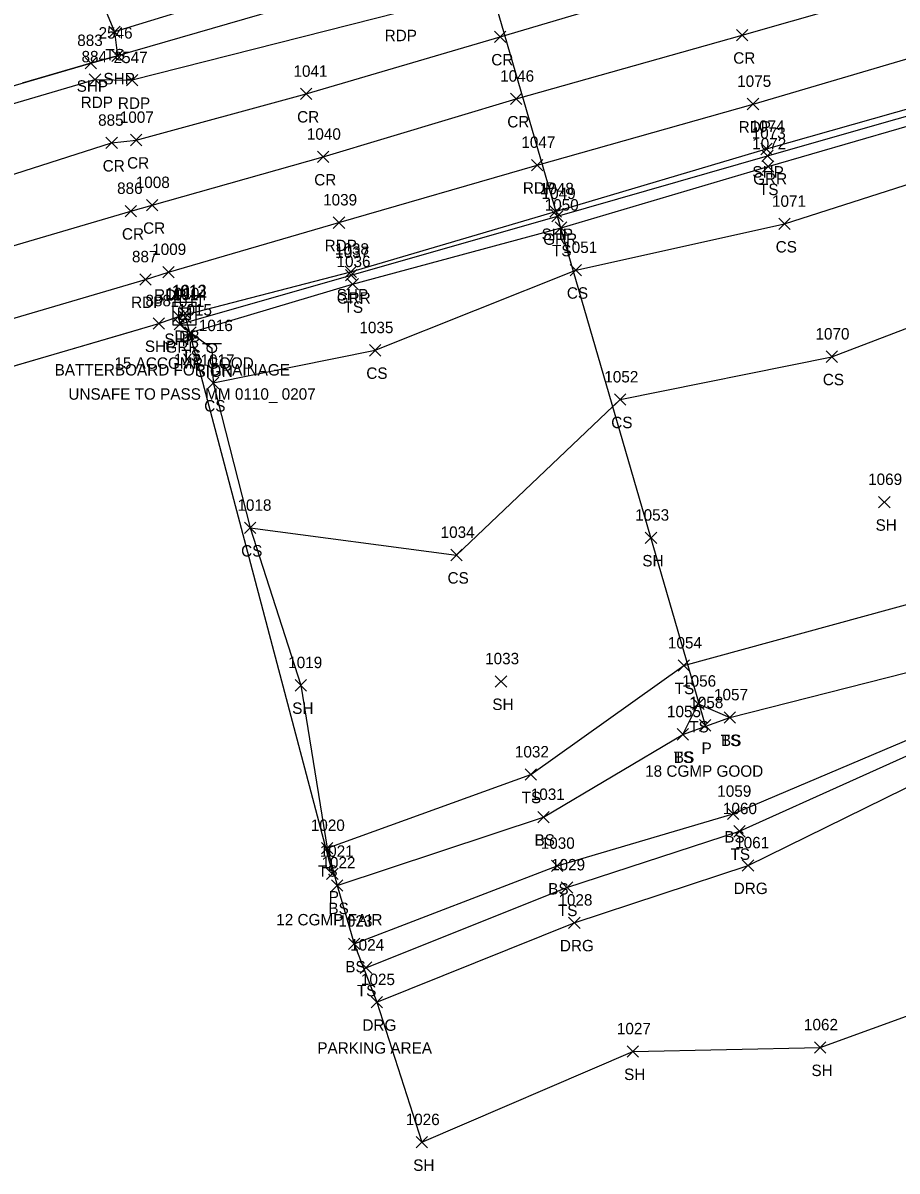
# Model space of a CAD drawing. Extents: x 49137 to 50946, y 9590 to 10709.
# Drawn here: x 49615.7 to 49768.6, y 9758.1 to 9959 of the extents above; entities that cross this region are included whole.
import ezdxf

# ---------------------------------------------------------------- set-up
doc = ezdxf.new("R2010")
doc.units = 0
for name, color, linetype in [('D_A', 7, 'Continuous'), ('D_C', 7, 'Continuous'), ('D_I', 7, 'Continuous'), ('D_TIC', 7, 'Continuous'), ('DCP', 7, 'Continuous'), ('DS', 7, 'Continuous'), ('L_A', 7, 'Continuous'), ('L_I', 7, 'Continuous'), ('L_TIC', 7, 'Continuous'), ('LELB', 7, 'Continuous'), ('LSOGP', 7, 'Continuous'), ('P_A', 7, 'Continuous'), ('P_I', 7, 'Continuous'), ('P_TIC', 7, 'Continuous'), ('PET', 7, 'Continuous'), ('PRC', 7, 'Continuous'), ('PSP', 7, 'Continuous'), ('R_A', 7, 'Continuous'), ('R_C', 7, 'Continuous'), ('R_I', 7, 'Continuous'), ('R_TIC', 7, 'Continuous'), ('RDG', 7, 'Continuous'), ('RGR', 7, 'Continuous'), ('S_A', 7, 'Continuous'), ('S_C', 7, 'Continuous'), ('S_I', 7, 'Continuous'), ('SSGN', 7, 'Continuous')]:
    doc.layers.add(name, color=color, linetype=linetype)

msp = doc.modelspace()

# ---------------------------------------------------------------- linework, layer by layer
at = {"layer": 'D_TIC'}
for points in [[(49643.11, 9907.2), (49645.11, 9909.2)], [(49645.11, 9907.2), (49643.11, 9909.2)], [(49643.13, 9906.49), (49645.13, 9908.49)], [(49645.13, 9906.49), (49643.13, 9908.49)], [(49734.05, 9835.12), (49736.05, 9837.12)], [(49736.05, 9835.12), (49734.05, 9837.12)], [(49668.84, 9809.12), (49670.84, 9811.12)], [(49670.84, 9809.12), (49668.84, 9811.12)]]:
    msp.add_lwpolyline(points, dxfattribs=at)
at = {"layer": 'DCP'}
for points in [[(49691.29, 9986.82), (49735.05, 9836.12)], [(49644.13, 9907.49), (49669.84, 9810.12)]]:
    msp.add_lwpolyline(points, dxfattribs=at)
at = {"layer": 'DS'}
for p, q in [((49641.97, 9910.13), (49645.97, 9910.13)), ((49641.97, 9906.13), (49641.97, 9910.13)), ((49645.97, 9910.13), (49645.97, 9906.13)), ((49642.97, 9907.13), (49642.97, 9909.13)), ((49642.97, 9909.13), (49644.97, 9909.13)), ((49643.98, 9908.13), (49643.98, 9908.13)), ((49643.98, 9908.13), (49643.98, 9908.13)), ((49644.97, 9909.13), (49644.97, 9907.13)), ((49645.97, 9906.13), (49641.97, 9906.13)), ((49644.97, 9907.13), (49642.97, 9907.13))]:
    msp.add_line(p, q, dxfattribs=at)
at = {"layer": 'L_TIC'}
for points in [[(49630.72, 9956.44), (49632.72, 9958.44)], [(49632.72, 9956.44), (49630.72, 9958.44)], [(49745.05, 9932.87), (49747.05, 9934.87)], [(49747.05, 9932.87), (49745.05, 9934.87)], [(49708.84, 9922.17), (49710.84, 9924.17)], [(49710.84, 9922.17), (49708.84, 9924.17)], [(49747.94, 9922.83), (49749.94, 9924.83)], [(49749.94, 9922.83), (49747.94, 9924.83)], [(49711.42, 9914.75), (49713.42, 9916.75)], [(49713.42, 9914.75), (49711.42, 9916.75)], [(49672.39, 9912.28), (49674.39, 9914.28)], [(49674.39, 9912.28), (49672.39, 9914.28)], [(49644.04, 9903.81), (49646.04, 9905.81)], [(49646.04, 9903.81), (49644.04, 9905.81)], [(49676.34, 9900.72), (49678.34, 9902.72)], [(49678.34, 9900.72), (49676.34, 9902.72)], [(49756.19, 9899.61), (49758.19, 9901.61)], [(49758.19, 9899.61), (49756.19, 9901.61)], [(49647.99, 9895.01), (49649.99, 9897.01)], [(49649.99, 9895.01), (49647.99, 9897.01)], [(49719.18, 9892.1), (49721.18, 9894.1)], [(49721.18, 9892.1), (49719.18, 9894.1)], [(49765.38, 9874.16), (49767.38, 9876.16)], [(49767.38, 9874.16), (49765.38, 9876.16)], [(49654.45, 9869.65), (49656.45, 9871.65)], [(49656.45, 9869.65), (49654.45, 9871.65)], [(49724.58, 9867.92), (49726.58, 9869.92)], [(49726.58, 9867.92), (49724.58, 9869.92)], [(49690.55, 9864.91), (49692.55, 9866.91)], [(49692.55, 9864.91), (49690.55, 9866.91)], [(49730.32, 9845.57), (49732.32, 9847.57)], [(49732.32, 9845.57), (49730.32, 9847.57)], [(49663.33, 9842.12), (49665.33, 9844.12)], [(49665.33, 9842.12), (49663.33, 9844.12)], [(49698.34, 9842.8), (49700.34, 9844.8)], [(49700.34, 9842.8), (49698.34, 9844.8)], [(49732.85, 9838.88), (49734.85, 9840.88)], [(49734.85, 9838.88), (49732.85, 9840.88)], [(49738.37, 9836.49), (49740.37, 9838.49)], [(49740.37, 9836.49), (49738.37, 9838.49)], [(49738.37, 9836.49), (49740.37, 9838.49)], [(49740.37, 9836.49), (49738.37, 9838.49)], [(49730.14, 9833.54), (49732.14, 9835.54)], [(49732.14, 9833.54), (49730.14, 9835.54)], [(49730.14, 9833.54), (49732.14, 9835.54)], [(49732.14, 9833.54), (49730.14, 9835.54)], [(49703.55, 9826.5), (49705.55, 9828.5)], [(49705.55, 9826.5), (49703.55, 9828.5)], [(49705.76, 9819.06), (49707.76, 9821.06)], [(49707.76, 9819.06), (49705.76, 9821.06)], [(49738.95, 9819.62), (49740.95, 9821.62)], [(49740.95, 9819.62), (49738.95, 9821.62)], [(49740.07, 9816.58), (49742.07, 9818.58)], [(49742.07, 9816.58), (49740.07, 9818.58)], [(49667.93, 9813.64), (49669.93, 9815.64)], [(49669.93, 9813.64), (49667.93, 9815.64)], [(49708.15, 9810.52), (49710.15, 9812.52)], [(49710.15, 9810.52), (49708.15, 9812.52)], [(49669.7, 9807.1), (49671.7, 9809.1)], [(49671.7, 9807.1), (49669.7, 9809.1)], [(49709.88, 9806.74), (49711.88, 9808.74)], [(49711.88, 9806.74), (49709.88, 9808.74)], [(49672.66, 9796.9), (49674.66, 9798.9)], [(49674.66, 9796.9), (49672.66, 9798.9)], [(49674.72, 9792.72), (49676.72, 9794.72)], [(49676.72, 9792.72), (49674.72, 9794.72)], [(49721.38, 9778.07), (49723.38, 9780.07)], [(49723.38, 9778.07), (49721.38, 9780.07)], [(49754.15, 9778.76), (49756.15, 9780.76)], [(49756.15, 9778.76), (49754.15, 9780.76)], [(49684.49, 9762.18), (49686.49, 9764.18)], [(49686.49, 9762.18), (49684.49, 9764.18)]]:
    msp.add_lwpolyline(points, dxfattribs=at)
at = {"layer": 'LELB'}
for points in [[(49707.17, 10012.1), (49710.58, 10002.74), (49713.22, 9991.71), (49709.24, 9979.98), (49678.52, 9971.76), (49631.72, 9957.44)], [(49648.99, 9896.01), (49677.34, 9901.72), (49712.42, 9915.75), (49748.94, 9923.83), (49795.33, 9938.72), (49840.71, 9952.18), (49888.53, 9965.97), (49924.25, 9972.55), (49947.18, 9982.02)], [(49670.7, 9808.1), (49706.76, 9820.06), (49731.14, 9834.54), (49739.37, 9837.49), (49777.2, 9847.1), (49820.15, 9864.91), (49860.04, 9878.97), (49899.33, 9895.75), (49907.79, 9901.19), (49920.26, 9900.95), (49937.62, 9910.99), (49944.21, 9929.08), (49950.2, 9948.45), (49953.39, 9966.85), (49956.28, 9979.26)], [(49655.45, 9870.65), (49691.55, 9865.91), (49720.18, 9893.1), (49757.19, 9900.61), (49801.8, 9917.58), (49846.63, 9930.43), (49892.92, 9944.18), (49914.34, 9953.17), (49928.67, 9955.31)], [(49668.93, 9814.64), (49704.55, 9827.5), (49731.32, 9846.57), (49773.04, 9858.01), (49814.49, 9881.23), (49855.73, 9893.51), (49903.67, 9913.36), (49925.03, 9924.95), (49933.37, 9938.84), (49930.22, 9947.23), (49929.09, 9952.46)], [(49645.04, 9904.81), (49673.39, 9913.28), (49709.84, 9923.17), (49746.05, 9933.87), (49791.91, 9947.2)], [(49673.66, 9797.9), (49709.15, 9811.52), (49739.95, 9820.62), (49781.06, 9838.09), (49823.28, 9856.66), (49863.52, 9873.12), (49910.58, 9889.54), (49938.11, 9900.03), (49942.19, 9872.49)], [(49675.72, 9793.72), (49710.88, 9807.74), (49741.07, 9817.58), (49781.98, 9836.04), (49824.42, 9852.68), (49865.21, 9869.56), (49911.79, 9886.53), (49935.6, 9895.74), (49942.19, 9872.49)], [(49731.14, 9834.54), (49733.85, 9839.88), (49739.37, 9837.49)]]:
    msp.add_lwpolyline(points, dxfattribs=at)
at = {"layer": 'LSOGP'}
for points in [[(49626.96, 9969.01), (49631.72, 9957.44), (49632.26, 9953.25), (49627.58, 9951.96), (49621.59, 9950.21), (49615.6, 9948.46)], [(49613.21, 9898.72), (49619.79, 9900.65), (49626.36, 9902.58), (49632.94, 9904.5), (49639.52, 9906.43), (49642.92, 9907.66), (49643.16, 9906.31), (49645.04, 9904.81), (49648.76, 9902.08), (49648.99, 9896.01), (49655.44, 9870.65), (49664.33, 9843.12), (49668.92, 9814.64), (49670.7, 9808.1), (49673.66, 9797.9), (49677.61, 9787.67), (49685.5, 9763.18), (49722.38, 9779.07), (49755.15, 9779.76), (49800.92, 9796.37)]]:
    msp.add_lwpolyline(points, dxfattribs=at)
at = {"layer": 'P_TIC'}
for points in [[(49740.53, 9955.86), (49742.53, 9957.86)], [(49742.53, 9955.86), (49740.53, 9957.86)], [(49698.21, 9955.56), (49700.21, 9957.56)], [(49700.21, 9955.56), (49698.21, 9957.56)], [(49631.26, 9952.25), (49633.26, 9954.25)], [(49633.26, 9952.25), (49631.26, 9954.25)], [(49626.58, 9950.96), (49628.58, 9952.96)], [(49628.58, 9950.96), (49626.58, 9952.96)], [(49627.33, 9948.1), (49629.33, 9950.1)], [(49629.33, 9948.1), (49627.33, 9950.1)], [(49633.84, 9947.96), (49635.84, 9949.96)], [(49635.84, 9947.96), (49633.84, 9949.96)], [(49664.25, 9945.57), (49666.25, 9947.57)], [(49666.25, 9945.57), (49664.25, 9947.57)], [(49701.01, 9944.71), (49703.01, 9946.71)], [(49703.01, 9944.71), (49701.01, 9946.71)], [(49742.42, 9943.81), (49744.42, 9945.81)], [(49744.42, 9943.81), (49742.42, 9945.81)], [(49630.24, 9937), (49632.24, 9939)], [(49632.24, 9937), (49630.24, 9939)], [(49634.51, 9937.51), (49636.51, 9939.51)], [(49636.51, 9937.51), (49634.51, 9939.51)], [(49744.77, 9935.94), (49746.77, 9937.94)], [(49746.77, 9935.94), (49744.77, 9937.94)], [(49667.24, 9934.56), (49669.24, 9936.56)], [(49669.24, 9934.56), (49667.24, 9936.56)], [(49704.67, 9933.13), (49706.67, 9935.13)], [(49706.67, 9933.13), (49704.67, 9935.13)], [(49637.31, 9926.11), (49639.31, 9928.11)], [(49639.31, 9926.11), (49637.31, 9928.11)], [(49633.61, 9925.08), (49635.61, 9927.08)], [(49635.61, 9925.08), (49633.61, 9927.08)], [(49707.9, 9925.02), (49709.9, 9927.02)], [(49709.9, 9925.02), (49707.9, 9927.02)], [(49670, 9923.06), (49672, 9925.06)], [(49672, 9923.06), (49670, 9925.06)], [(49640.19, 9914.4), (49642.19, 9916.4)], [(49642.19, 9914.4), (49640.19, 9916.4)], [(49672.06, 9914.45), (49674.06, 9916.45)], [(49674.06, 9914.45), (49672.06, 9916.45)], [(49636.15, 9913.12), (49638.15, 9915.12)], [(49638.15, 9913.12), (49636.15, 9915.12)], [(49638.51, 9905.43), (49640.51, 9907.43)], [(49640.51, 9905.43), (49638.51, 9907.43)], [(49641.92, 9906.66), (49643.92, 9908.66)], [(49643.92, 9906.66), (49641.92, 9908.66)]]:
    msp.add_lwpolyline(points, dxfattribs=at)
at = {"layer": 'PET'}
for points in [[(49773.46, 9981.58), (49739, 9973.69), (49713.75, 9967.94), (49681.51, 9960.8), (49634.84, 9948.96)], [(49641.19, 9915.4), (49671, 9924.06), (49705.67, 9934.13), (49743.42, 9944.81), (49788.35, 9958.02)], [(49139.98, 9814.46), (49187.62, 9825.63), (49235.89, 9837.72), (49282.96, 9850.62), (49341.7, 9866.23), (49395.76, 9882.14), (49442.91, 9895.57), (49507.79, 9914.28), (49580.35, 9934.99), (49628.33, 9949.1)], [(49628.33, 9949.1), (49634.84, 9948.96)], [(49145.45, 9779.72), (49195.9, 9790.39), (49243.81, 9802.52), (49292.08, 9816.01), (49347.68, 9831.32), (49405.1, 9847.77), (49451.91, 9860.81), (49518.83, 9880.22), (49586.17, 9899.12), (49637.15, 9914.12)], [(49637.15, 9914.12), (49641.19, 9915.4)]]:
    msp.add_lwpolyline(points, dxfattribs=at)
at = {"layer": 'PRC'}
for points in [[(49635.51, 9938.51), (49665.25, 9946.57), (49699.21, 9956.56), (49739.04, 9968.37), (49782.75, 9980.26), (49832.37, 9994.06), (49891.41, 10012.39)], [(49638.31, 9927.11), (49668.24, 9935.56), (49702.01, 9945.71), (49741.53, 9956.86), (49785.57, 9969.42)], [(49141.63, 9803.74), (49190.3, 9814.27), (49238.59, 9826.33), (49285.89, 9838.96), (49342.49, 9854.35), (49398.46, 9872.19), (49445.8, 9882.03), (49511.62, 9902.86), (49582.21, 9922.35), (49631.24, 9938)], [(49631.24, 9938), (49635.51, 9938.51)], [(49143.26, 9791.38), (49192.3, 9802.18), (49241.44, 9814.1), (49289.03, 9827.2), (49344.74, 9842.62), (49402, 9859.5), (49448.68, 9872.62), (49515.07, 9891.58), (49584.01, 9911.21), (49634.61, 9926.08)], [(49634.61, 9926.08), (49638.31, 9927.11)]]:
    msp.add_lwpolyline(points, dxfattribs=at)
at = {"layer": 'PSP'}
for points in [[(49769.91, 9990.82), (49738.16, 9982.81), (49714.76, 9978.24), (49679.34, 9966.88), (49632.26, 9953.25)], [(49138.92, 9820.06), (49187.08, 9830.78), (49234.52, 9842.08), (49282.61, 9853.37), (49341, 9869.78), (49394.44, 9884.65), (49442.1, 9898.6), (49506.41, 9917), (49579.64, 9937.94), (49627.58, 9951.96)], [(49627.58, 9951.96), (49632.26, 9953.25)], [(49642.92, 9907.66), (49673.06, 9915.45), (49708.9, 9926.02), (49745.77, 9936.94), (49791.02, 9949.79)], [(49639.51, 9906.43), (49642.92, 9907.66)], [(49146.91, 9772.57), (49197.62, 9783.46), (49245.56, 9795.29), (49292.72, 9808.44), (49349.12, 9824.34), (49407.39, 9841.09), (49453.87, 9853.42), (49521.5, 9872.52), (49586.9, 9891), (49639.51, 9906.43)]]:
    msp.add_lwpolyline(points, dxfattribs=at)
at = {"layer": 'R_TIC'}
for points in [[(49744.96, 9934.74), (49746.96, 9936.74)], [(49746.96, 9934.74), (49744.96, 9936.74)], [(49708.23, 9924.18), (49710.23, 9926.18)], [(49710.23, 9924.18), (49708.23, 9926.18)], [(49672.13, 9913.88), (49674.13, 9915.88)], [(49674.13, 9913.88), (49672.13, 9915.88)], [(49642.15, 9905.31), (49644.15, 9907.31)], [(49644.15, 9905.31), (49642.15, 9907.31)], [(49741.55, 9810.6), (49743.55, 9812.6)], [(49743.55, 9810.6), (49741.55, 9812.6)], [(49711.16, 9800.58), (49713.16, 9802.58)], [(49713.16, 9800.58), (49711.16, 9802.58)], [(49676.61, 9786.68), (49678.61, 9788.68)], [(49678.61, 9786.68), (49676.61, 9788.68)]]:
    msp.add_lwpolyline(points, dxfattribs=at)
at = {"layer": 'RDG'}
msp.add_lwpolyline([(49677.61, 9787.68), (49712.16, 9801.58), (49742.55, 9811.6), (49783.63, 9831.79), (49826.52, 9847.59), (49866.61, 9865.33), (49912.42, 9883.28), (49934.02, 9891.85), (49936.62, 9871.41), (49942.28, 9849.04), (49938.19, 9834.18), (49937.17, 9823.88), (49941.18, 9816.67), (49948.22, 9818.93)], dxfattribs=at)
at = {"layer": 'RGR'}
msp.add_lwpolyline([(49643.15, 9906.31), (49673.13, 9914.88), (49709.23, 9925.18), (49745.96, 9935.74), (49791.34, 9948.66)], dxfattribs=at)
at = {"layer": 'SSGN'}
for p, q in [((49647.13, 9902.94), (49650.46, 9902.94)), ((49648.77, 9902.1), (49648.77, 9902.1))]:
    msp.add_line(p, q, dxfattribs=at)
msp.add_circle((49648.77, 9902.1), 0.833, dxfattribs=at)

# ---------------------------------------------------------------- texts
at = {"layer": 'D_A'}
for s, p in [('DIB', (49642.21, 9903.2)), ('DI', (49643.03, 9903.13)), ('P', (49643.51, 9902.49)), ('P', (49734.42, 9831.12)), ('P', (49669.21, 9805.12))]:
    msp.add_text(s, height=2, dxfattribs=at).set_placement(p)
at = {"layer": 'D_C'}
for s, p in [('15 ACCGMP GOOD', (49631.72, 9898.49)), ('1X2', (49642.12, 9899.13)), ('18 CGMP GOOD', (49724.55, 9827.12)), ('12 CGMP FAIR', (49660.03, 9801.12))]:
    msp.add_text(s, height=2, dxfattribs=at).set_placement(p)
at = {"layer": 'D_I'}
for s, p in [('1012', (49641.77, 9911.13)), ('1013', (49641.9, 9911.2)), ('1014', (49641.93, 9910.49)), ('1058', (49732.28, 9839.12)), ('1021', (49667.63, 9813.12))]:
    msp.add_text(s, height=2, dxfattribs=at).set_placement(p)
at = {"layer": 'L_A'}
for s, p in [('TS', (49630.13, 9952.44)), ('TS', (49744.46, 9928.87)), ('TS', (49708.25, 9918.17)), ('CS', (49747.38, 9918.83)), ('CS', (49710.86, 9910.75)), ('TS', (49671.8, 9908.28)), ('TS', (49643.45, 9899.81)), ('CS', (49675.78, 9896.72)), ('CS', (49755.63, 9895.61)), ('CS', (49647.43, 9891.01)), ('CS', (49718.62, 9888.1)), ('SH', (49764.86, 9870.16)), ('CS', (49653.89, 9865.65)), ('SH', (49724.06, 9863.92)), ('CS', (49689.99, 9860.91)), ('TS', (49729.73, 9841.57)), ('SH', (49662.82, 9838.12)), ('SH', (49697.82, 9838.8)), ('TS', (49732.26, 9834.88)), ('TS', (49737.78, 9832.49)), ('BS', (49737.81, 9832.49)), ('TS', (49729.55, 9829.54)), ('BS', (49729.58, 9829.54)), ('TS', (49702.95, 9822.5)), ('BS', (49705.2, 9815.06)), ('BS', (49738.39, 9815.62)), ('TS', (49739.48, 9812.58)), ('TS', (49667.34, 9809.64)), ('BS', (49707.59, 9806.52)), ('BS', (49669.14, 9803.1)), ('TS', (49709.29, 9802.74)), ('BS', (49672.1, 9792.9)), ('TS', (49674.13, 9788.72)), ('SH', (49720.87, 9774.07)), ('SH', (49753.64, 9774.76)), ('SH', (49683.98, 9758.18))]:
    msp.add_text(s, height=2, dxfattribs=at).set_placement(p)
at = {"layer": 'L_I'}
for s, p in [('1072', (49743.28, 9936.87)), ('1050', (49706.98, 9926.17)), ('1071', (49746.74, 9926.83)), ('1051', (49710.22, 9918.75)), ('1036', (49670.57, 9916.28)), ('1015', (49642.83, 9907.81)), ('1035', (49674.57, 9904.72)), ('1070', (49754.34, 9903.61)), ('1017', (49646.79, 9899.01)), ('1052', (49717.41, 9896.1)), ('1069', (49763.55, 9878.16)), ('1018', (49653.24, 9873.65)), ('1053', (49722.8, 9871.92)), ('1034', (49688.78, 9868.91)), ('1054', (49728.54, 9849.57)), ('1019', (49662.12, 9846.12)), ('1033', (49696.56, 9846.8)), ('1056', (49731.02, 9842.88)), ('1057', (49736.6, 9840.49)), ('1057', (49736.6, 9840.49)), ('1055', (49728.37, 9837.54)), ('1055', (49728.37, 9837.54)), ('1032', (49701.77, 9830.5)), ('1031', (49704.55, 9823.06)), ('1059', (49737.17, 9823.62)), ('1060', (49738.16, 9820.58)), ('1020', (49666.07, 9817.64)), ('1030', (49706.29, 9814.52)), ('1022', (49667.93, 9811.1)), ('1029', (49708.1, 9810.74)), ('1023', (49670.89, 9800.9)), ('1024', (49672.95, 9796.72)), ('1027', (49719.61, 9782.07)), ('1062', (49752.33, 9782.76)), ('1026', (49682.67, 9766.18))]:
    msp.add_text(s, height=2, dxfattribs=at).set_placement(p)
at = {"layer": 'P_A'}
for s, p in [('RDP', (49678.99, 9955.8)), ('CR', (49739.96, 9951.86)), ('CR', (49697.64, 9951.56)), ('SHP', (49629.8, 9948.25)), ('SHP', (49625.12, 9946.96)), ('RDP', (49625.82, 9944.1)), ('RDP', (49632.33, 9943.96)), ('CR', (49663.68, 9941.57)), ('CR', (49700.44, 9940.71)), ('RDP', (49740.91, 9939.81)), ('CR', (49633.94, 9933.51)), ('CR', (49629.67, 9933)), ('SHP', (49743.31, 9931.94)), ('CR', (49666.67, 9930.56)), ('RDP', (49703.16, 9929.13)), ('CR', (49636.74, 9922.11)), ('CR', (49633.04, 9921.08)), ('SHP', (49706.44, 9921.02)), ('RDP', (49668.49, 9919.06)), ('RDP', (49638.67, 9910.4)), ('SHP', (49670.6, 9910.45)), ('RDP', (49634.64, 9909.12)), ('SHP', (49637.05, 9901.43)), ('SHP', (49640.46, 9902.66))]:
    msp.add_text(s, height=2, dxfattribs=at).set_placement(p)
at = {"layer": 'P_I'}
for s, p in [('2546', (49628.95, 9956.25)), ('883', (49625.22, 9954.96)), ('884', (49625.97, 9952.1)), ('2547', (49631.58, 9951.96)), ('1041', (49663.04, 9949.57)), ('1046', (49699.19, 9948.71)), ('1075', (49740.65, 9947.81)), ('885', (49628.87, 9941)), ('1007', (49632.66, 9941.51)), ('1074', (49743, 9939.94)), ('1040', (49665.38, 9938.56)), ('1047', (49702.9, 9937.13)), ('1008', (49635.46, 9930.11)), ('886', (49632.19, 9929.08)), ('1048', (49706.13, 9929.02)), ('1039', (49668.22, 9927.06)), ('1009', (49638.33, 9918.4)), ('1038', (49670.29, 9918.45)), ('887', (49634.79, 9917.12)), ('888', (49637.15, 9909.43)), ('1010', (49640.63, 9910.66))]:
    msp.add_text(s, height=2, dxfattribs=at).set_placement(p)
at = {"layer": 'R_A'}
for s, p in [('GRR', (49743.45, 9930.74)), ('GRR', (49706.72, 9920.18)), ('GRR', (49670.61, 9909.88)), ('GRR', (49640.64, 9901.31)), ('DRG', (49740.04, 9806.6)), ('DRG', (49709.64, 9796.58)), ('DRG', (49675.1, 9782.68))]:
    msp.add_text(s, height=2, dxfattribs=at).set_placement(p)
at = {"layer": 'R_C'}
for s, p in [('BATTERBOARD FOR DRAINAGE', (49621.26, 9897.31)), ('PARKING AREA', (49667.21, 9778.68))]:
    msp.add_text(s, height=2, dxfattribs=at).set_placement(p)
at = {"layer": 'R_I'}
for s, p in [('1073', (49743.19, 9938.74)), ('1049', (49706.45, 9928.18)), ('1037', (49670.35, 9917.88)), ('1011', (49641.52, 9909.31)), ('1061', (49740.3, 9814.6)), ('1028', (49709.38, 9804.58)), ('1025', (49674.84, 9790.68))]:
    msp.add_text(s, height=2, dxfattribs=at).set_placement(p)
at = {"layer": 'S_A'}
msp.add_text('SIGN', height=2, dxfattribs=at).set_placement((49645.91, 9897.08))
at = {"layer": 'S_C'}
msp.add_text('UNSAFE TO PASS MM 0110_ 0207', height=2, dxfattribs=at).set_placement((49623.67, 9893.08))
at = {"layer": 'S_I'}
msp.add_text('1016', height=2, dxfattribs=at).set_placement((49646.49, 9905.08))

doc.saveas('drawing.dxf')
